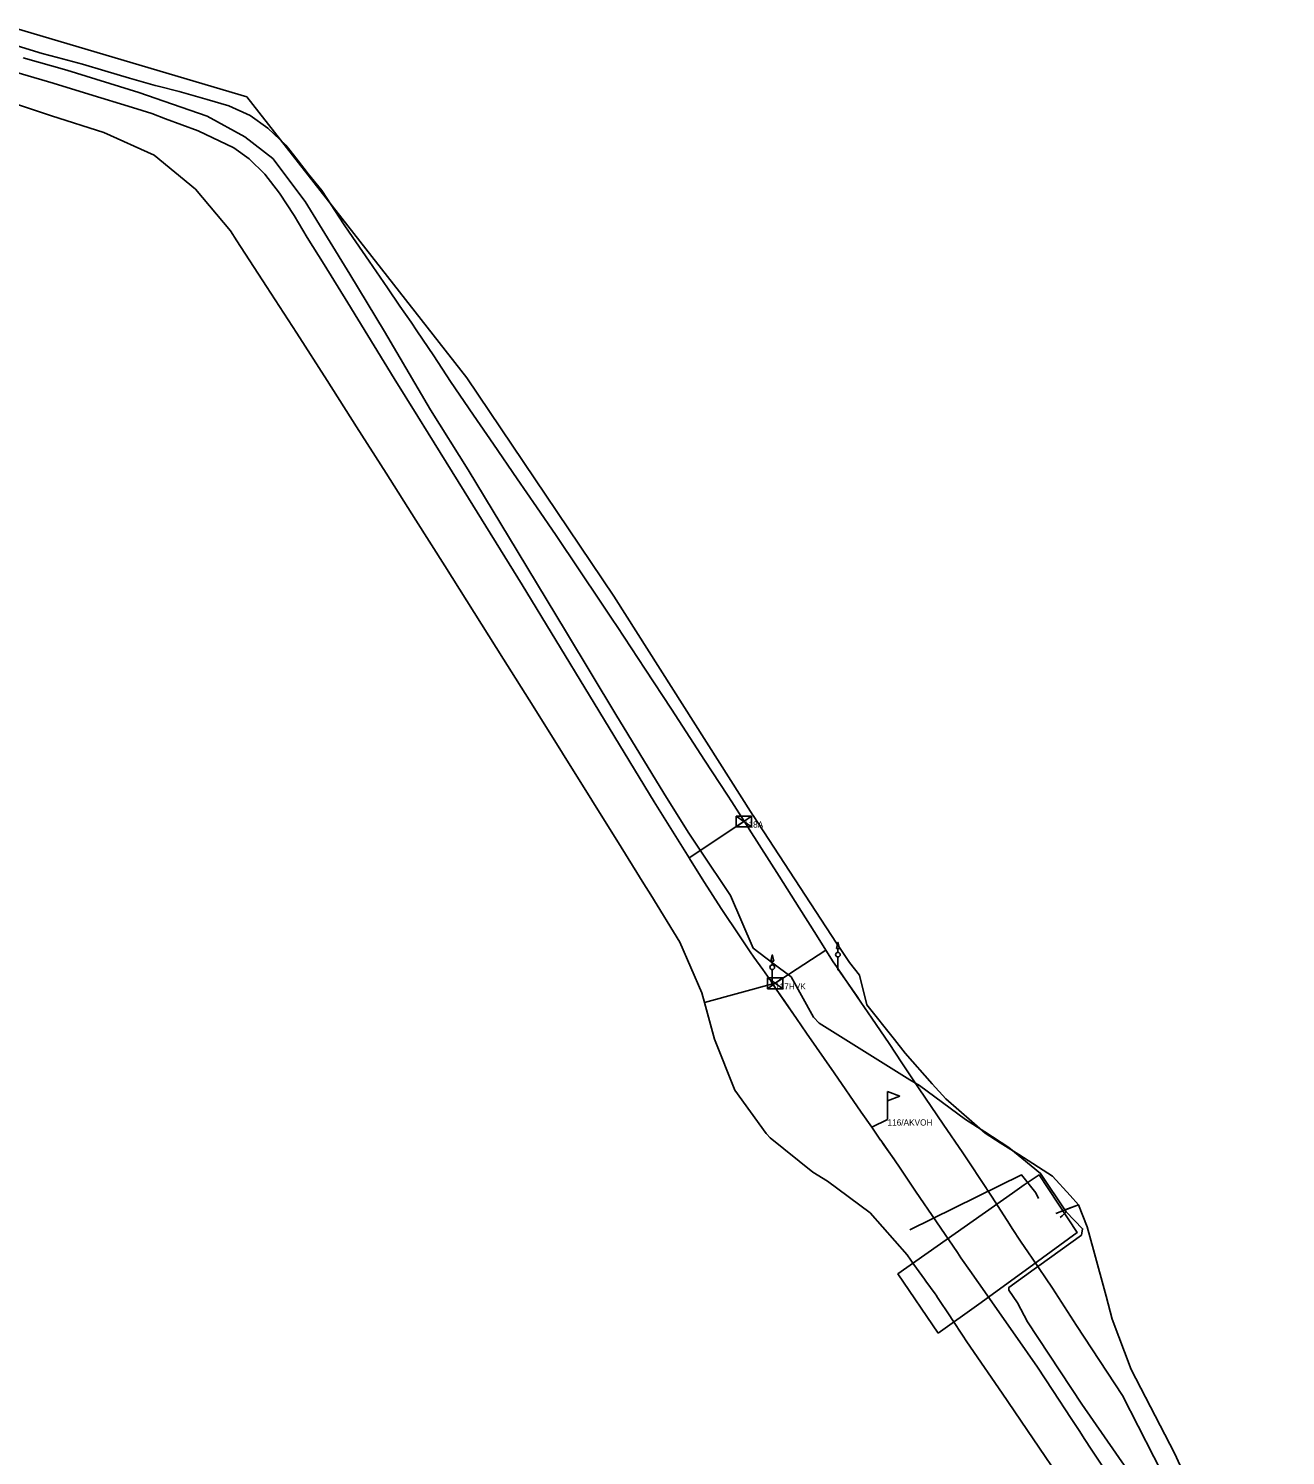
# Model space of a CAD drawing. Extents: x -636745 to -623523, y -1149222 to -1137851.
# Drawn here: x -634819.9 to -634412.2, y -1139972 to -1139509.3 of the extents above; entities that cross this region are included whole.
import ezdxf

# ---------------------------------------------------------------- set-up
doc = ezdxf.new("R2010")
doc.units = 0
for name, color, linetype in [('Chránička', 7, 'Continuous'), ('Elektropřipojka', 7, 'Continuous'), ('KVO', 7, 'Continuous'), ('Metalický kabel TELCO', 7, 'Continuous'), ('obecný popis PKO', 7, 'Continuous'), ('Oplocení', 7, 'Continuous'), ('Optický kabel  TELCO', 7, 'Continuous'), ('PKO Propojovací kabel', 7, 'Continuous'), ('Plynovody - DN1000', 7, 'Continuous'), ('Plynovody - DN900', 7, 'Continuous'), ('Popis PO', 7, 'Continuous'), ('Propojovací objekt', 7, 'Continuous'), ('Čichačka', 7, 'Continuous')]:
    doc.layers.add(name, color=color, linetype=linetype)

# ---------------------------------------------------------------- blocks, each defined once
blk = doc.blocks.new('2.12')
at = {"layer": 'Propojovací objekt'}
for p, q in [((-0.25, 0.175), (0.25, 0.175)), ((-0.25, 0.175), (0, 0)), ((-0.25, -0.175), (-0.25, 0.175)), ((0, 0), (-0.25, -0.175)), ((0.25, 0.175), (0, 0)), ((0, 0), (0.25, -0.175)), ((0.25, -0.175), (0.25, 0.175)), ((-0.25, -0.175), (0.25, -0.175))]:
    blk.add_line(p, q, dxfattribs=at)
blk = doc.blocks.new('2.13')
at = {"layer": 'KVO'}
for p, q in [((0, 0.6), (0, 0.9)), ((0, 0.9), (0.4, 0.75)), ((0.4, 0.75), (0, 0.6)), ((0, 0.6), (0, 0))]:
    blk.add_line(p, q, dxfattribs=at)
blk = doc.blocks.new('1.18')
at = {"layer": 'Čichačka'}
for p, q in [((0, 0.575), (0, 0.7)), ((0, 0), (0, 0.425))]:
    blk.add_line(p, q, dxfattribs=at)
blk.add_lwpolyline([(-0.05, 0.7), (0.05, 0.7), (0, 0.9)], close=True, dxfattribs=at)
blk.add_circle((0, 0.5), 0.075, dxfattribs=at)

msp = doc.modelspace()

# ---------------------------------------------------------------- linework, layer by layer
at = {"layer": 'Chránička'}
for points in [[(-634549.996, -1139824.921), (-634555.609, -1139816.737), (-634557.648, -1139813.763)], [(-634570.413, -1139830.912), (-634572.078, -1139828.487), (-634573.258, -1139826.767), (-634574.831, -1139824.475), (-634576.645, -1139821.83), (-634577.396, -1139820.735), (-634578.222, -1139819.53), (-634579.226, -1139818.065)], [(-634538.898, -1139876.408), (-634540.406, -1139874.231), (-634542.479, -1139871.24), (-634543.527, -1139869.728)]]:
    msp.add_lwpolyline(points, dxfattribs=at)
at = {"layer": 'Elektropřipojka'}
msp.add_lwpolyline([(-634534.07, -1139898.79), (-634497.88, -1139880.93), (-634493.21, -1139886.75), (-634492.31, -1139888.65)], dxfattribs=at)
at = {"layer": 'Metalický kabel TELCO'}
for points in [[(-634486.72, -1139893.45), (-634482.586, -1139891.907), (-634479.38, -1139890.71), (-634482.133, -1139887.673), (-634487.8, -1139881.42), (-634498.754, -1139874.414), (-634504.737, -1139870.587), (-634509.61, -1139867.47), (-634513.955, -1139863.713), (-634522.46, -1139856.36), (-634526.802, -1139851.459), (-634535.57, -1139841.56), (-634539.08, -1139837.109), (-634547.99, -1139825.81), (-634550.46, -1139816.19), (-634553.686, -1139812.136), (-634556.878, -1139807.252), (-634557.823, -1139805.806), (-634584.889, -1139764.413), (-634584.967, -1139764.293), (-634630.115, -1139693.305), (-634677.807, -1139622.523), (-634749.134, -1139531.373), (-634823.971, -1139509.257)], [(-634412.249, -1140049.441), (-634448.26, -1139971.25), (-634462.33, -1139944.09), (-634468.41, -1139927.79), (-634470.452, -1139920.256), (-634474.518, -1139905.25), (-634476.52, -1139897.86), (-634479.38, -1139890.71), (-634486.72, -1139893.45)]]:
    msp.add_lwpolyline(points, dxfattribs=at)
at = {"layer": 'Oplocení'}
msp.add_lwpolyline([(-634524.85, -1139932.32), (-634537.97, -1139913.1), (-634500.84, -1139886.94), (-634497, -1139884.23), (-634492.18, -1139880.93), (-634479.82, -1139899.67), (-634496.684, -1139911.963), (-634511.66, -1139922.88)], close=True, dxfattribs=at)
at = {"layer": 'Optický kabel  TELCO'}
for points in [[(-634483.37, -1139892.97), (-634491.658, -1139880.487), (-634501.96, -1139872.07), (-634509.79, -1139866.97), (-634516.08, -1139863.01), (-634530.98, -1139852.04), (-634534.034, -1139850.134), (-634563.5, -1139831.75), (-634565.367, -1139829.889), (-634572.631, -1139816.765), (-634578.502, -1139812.319), (-634584.88, -1139807.49), (-634592.21, -1139790.34), (-634602.042, -1139775.724), (-634605.96, -1139769.9), (-634613.91, -1139757.23), (-634629.44, -1139731.73), (-634645.44, -1139705.07), (-634661.41, -1139678.63), (-634677.32, -1139652.36), (-634689.57, -1139632.88), (-634704.45, -1139607.46), (-634715.72, -1139588.93), (-634730.23, -1139565.29), (-634740.72, -1139551.43), (-634749.74, -1139544.42), (-634762.04, -1139537.69), (-634773.22, -1139533.78), (-634784.21, -1139530.02), (-634807.51, -1139522.79), (-634821.64, -1139518.75)], [(-634463.6, -1139976.5), (-634478.32, -1139955.34), (-634495.9, -1139928.61), (-634499.12, -1139922.46), (-634502.014, -1139918.396), (-634501.927, -1139917.443), (-634493.734, -1139911.551), (-634492.273, -1139910.499), (-634478.387, -1139900.503), (-634478.044, -1139898.426), (-634483.37, -1139892.97)], [(-634483.37, -1139892.97), (-634484.68, -1139894.232), (-634485.284, -1139894.814)]]:
    msp.add_lwpolyline(points, dxfattribs=at)
at = {"layer": 'PKO Propojovací kabel'}
for p, q in [((-634587.9, -1139766.38), (-634605.683, -1139778.139)), ((-634587.9, -1139766.38), (-634587.81, -1139766.327)), ((-634577.79, -1139818.86), (-634561.334, -1139808.079)), ((-634577.79, -1139818.86), (-634600.646, -1139825.102)), ((-634577.79, -1139818.86), (-634579.5, -1139817.666)), ((-634541.32, -1139862.977), (-634546.427, -1139865.544))]:
    msp.add_line(p, q, dxfattribs=at)
at = {"layer": 'Plynovody - DN1000'}
for points in [[(-634525.067, -1139920.705), (-634525.593, -1139919.933), (-634525.82, -1139919.6), (-634528.87, -1139915.39), (-634529.34, -1139914.74), (-634532.742, -1139910.041), (-634533.798, -1139908.583), (-634534.98, -1139906.95), (-634546.97, -1139893.33), (-634560.78, -1139883.05), (-634565.59, -1139880.09), (-634579.35, -1139869), (-634580.53, -1139867.64), (-634580.64, -1139867.52), (-634590.85, -1139853.47), (-634597.41, -1139836.95), (-634600.646, -1139825.102), (-634601.52, -1139821.9), (-634608.64, -1139805.5), (-634618.14, -1139790.16), (-634620.38, -1139786.554), (-634627.73, -1139774.72), (-634637.25, -1139759.43), (-634646.75, -1139744.22), (-634656.25, -1139729.04), (-634665.87, -1139713.73), (-634675.4, -1139698.64), (-634684.96, -1139683.52), (-634694.33, -1139668.72), (-634703.99, -1139653.41), (-634713.53, -1139638.36), (-634723.1, -1139623.36), (-634732.93, -1139608.07), (-634742.76, -1139592.92), (-634752.41, -1139578.08), (-634754.48, -1139574.89), (-634765.77, -1139561.35), (-634779.21, -1139550.27), (-634795.55, -1139542.97), (-634812.54, -1139537.54), (-634829.5, -1139531.92)], [(-634484.26, -1139981), (-634494.04, -1139966.54), (-634504.15, -1139951.76), (-634514.39, -1139936.84), (-634515.767, -1139934.759), (-634516.764, -1139933.252), (-634520.314, -1139927.886), (-634521.124, -1139926.662), (-634521.561, -1139926.001), (-634524.42, -1139921.68), (-634524.644, -1139921.343), (-634525.067, -1139920.705)]]:
    msp.add_lwpolyline(points, dxfattribs=at)
at = {"layer": 'Plynovody - DN900'}
for points in [[(-634498.17, -1139902.49), (-634500.919, -1139898.314), (-634501.81, -1139896.96), (-634507.414, -1139888.162), (-634514.557, -1139877.404), (-634516.91, -1139873.86), (-634523.315, -1139864.481), (-634531.082, -1139853.11), (-634536.667, -1139844.629), (-634540.785, -1139838.366), (-634546.403, -1139830.162), (-634549.996, -1139824.921), (-634551.408, -1139822.862), (-634557.187, -1139814.435), (-634557.648, -1139813.763), (-634557.857, -1139813.459), (-634558.96, -1139811.85), (-634561.334, -1139808.079), (-634564.392, -1139803.223), (-634569.96, -1139794.38), (-634576.495, -1139784.095), (-634586.164, -1139768.908), (-634587.81, -1139766.327), (-634591.815, -1139760.05), (-634593.2, -1139757.88), (-634600.662, -1139746.532), (-634611.441, -1139729.982), (-634619.916, -1139716.992), (-634629.04, -1139703.204), (-634630.644, -1139700.78), (-634634.108, -1139695.547), (-634648.847, -1139673.685), (-634655.225, -1139664.37), (-634661.429, -1139655.308), (-634669.142, -1139644.044), (-634675.622, -1139634.58), (-634683.085, -1139623.68), (-634688.512, -1139615.422), (-634693.954, -1139607.306), (-634695.877, -1139604.457), (-634699.46, -1139599.23), (-634703.489, -1139593.353), (-634709.479, -1139584.692), (-634715.985, -1139575.296), (-634717.616, -1139572.867), (-634724.77, -1139561.8), (-634729.199, -1139556.346), (-634730.621, -1139554.563), (-634733.25, -1139551.188), (-634735.23, -1139548.646), (-634736.45, -1139547.08), (-634742.29, -1139541.56), (-634748.06, -1139537.48), (-634754.96, -1139534.28), (-634761.971, -1139532.218), (-634768.852, -1139530.279), (-634771.11, -1139529.65), (-634777.921, -1139527.967), (-634778.88, -1139527.73), (-634787.18, -1139525.33), (-634795.172, -1139522.975), (-634802.45, -1139520.83), (-634810.553, -1139518.647), (-634815.475, -1139517.312), (-634825.077, -1139514.442)], [(-634514.68, -1139911.99), (-634517.494, -1139907.857), (-634518.63, -1139906.19), (-634532.287, -1139886.217), (-634537.483, -1139878.449), (-634538.898, -1139876.408), (-634539.305, -1139875.82), (-634541.099, -1139873.231), (-634543.527, -1139869.728), (-634543.551, -1139869.693), (-634546.427, -1139865.544), (-634549.823, -1139860.645), (-634558.634, -1139847.931), (-634567.612, -1139834.977), (-634570.849, -1139830.28), (-634575.029, -1139824.185), (-634577.621, -1139820.407), (-634578.475, -1139819.161), (-634578.783, -1139818.712), (-634578.817, -1139818.663), (-634579.226, -1139818.065), (-634579.478, -1139817.698), (-634579.5, -1139817.666), (-634581.815, -1139814.345), (-634584.669, -1139810.348), (-634585.91, -1139808.61), (-634589.122, -1139803.822), (-634595.336, -1139794.556), (-634600.635, -1139786.179), (-634605.2, -1139778.914), (-634605.683, -1139778.139), (-634616.973, -1139760.013), (-634637.96, -1139725.523), (-634659.792, -1139689.691), (-634678.674, -1139659.292), (-634690.321, -1139640.51), (-634693.714, -1139635.04), (-634701.3, -1139622.733), (-634716.325, -1139598.177), (-634724.02, -1139585.82), (-634729.57, -1139577.05), (-634733.82, -1139569.9), (-634738.52, -1139562.64), (-634743.31, -1139556.43), (-634748.34, -1139551.54), (-634753.35, -1139547.91), (-634764.93, -1139542.4), (-634775.535, -1139538.496), (-634779.98, -1139536.86), (-634786.211, -1139534.893), (-634800.384, -1139530.49), (-634811.973, -1139526.923), (-634833.738, -1139520.598)], [(-634449.81, -1139982.39), (-634465.13, -1139952.56), (-634479.982, -1139929.843), (-634487.857, -1139917.672), (-634494.449, -1139907.956), (-634495.615, -1139906.244), (-634498.17, -1139902.49)], [(-634463.6, -1139987.379), (-634475.24, -1139969.89), (-634477.302, -1139966.765), (-634479.203, -1139963.861), (-634481.78, -1139959.923), (-634487.698, -1139950.878), (-634492.681, -1139943.297), (-634499.917, -1139932.903), (-634511.857, -1139915.988), (-634514.68, -1139911.99)]]:
    msp.add_lwpolyline(points, dxfattribs=at)

# ---------------------------------------------------------------- block references
at = {"layer": 'KVO', "xscale": 10, "yscale": 10}
msp.add_blockref('2.13', (-634541.32, -1139862.977), dxfattribs=at)
at = {"layer": 'Propojovací objekt', "xscale": 10, "yscale": 10}
for p in [(-634587.9, -1139766.38), (-634577.79, -1139818.86)]:
    msp.add_blockref('2.12', p, dxfattribs=at)
at = {"layer": 'Čichačka', "xscale": 10, "yscale": 10}
for p in [(-634557.4, -1139814.57), (-634578.7, -1139818.66)]:
    msp.add_blockref('1.18', p, dxfattribs=at)

# ---------------------------------------------------------------- texts
at = {"layer": 'obecný popis PKO'}
for s, p in [('118A', (-634587.9, -1139768.38)), ('117HVK', (-634577.79, -1139820.86))]:
    msp.add_text(s, height=2, dxfattribs=at).set_placement(p)
at = {"layer": 'Popis PO'}
msp.add_text('116/AKVOH', height=2, dxfattribs=at).set_placement((-634541.32, -1139864.977))

doc.saveas('drawing.dxf')
